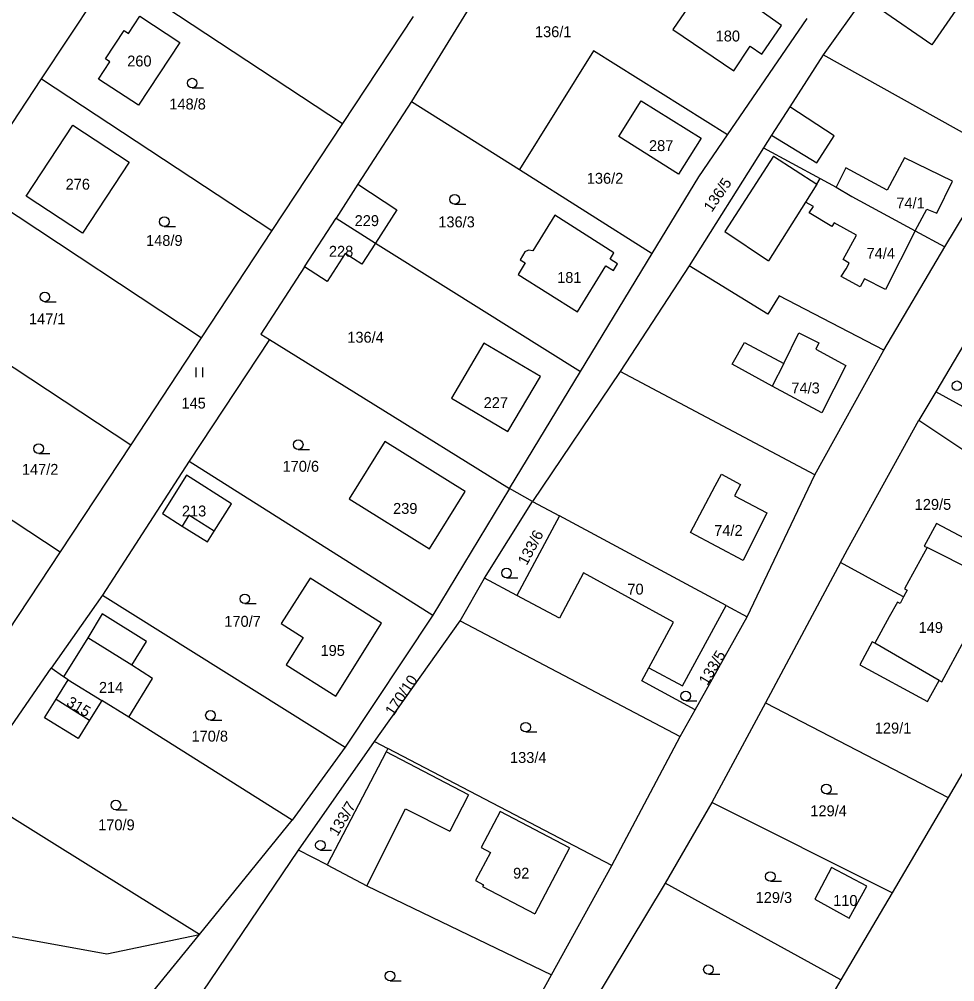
# Model space of a CAD drawing. Extents: x -747333 to -743907, y -1134120 to -1130051.
# Drawn here: x -746482.5 to -746336.6, y -1131946.1 to -1131796 of the extents above; entities that cross this region are included whole.
import ezdxf

# ---------------------------------------------------------------- set-up
doc = ezdxf.new("R2010")
doc.units = 0
for name, color, linetype in [('Hranice parcel', 7, 'Continuous'), ('Parcelní čísla', 7, 'Continuous'), ('Vnitřní kresba', 7, 'Continuous'), ('Značky kultur', 7, 'Continuous')]:
    doc.layers.add(name, color=color, linetype=linetype)

msp = doc.modelspace()

# ---------------------------------------------------------------- linework, layer by layer
at = {"layer": 'Hranice parcel'}
for p, q in [((-746343.18, -1131781.93), (-746357.15, -1131801.57)), ((-746478.99, -1131805.28), (-746467.98, -1131788.59)), ((-746467.98, -1131788.59), (-746432.08, -1131812.26)), ((-746421.07, -1131795.57), (-746432.08, -1131812.26)), ((-746372.05, -1131814.02), (-746359.64, -1131795.9)), ((-746329.51, -1131817), (-746357.15, -1131801.57)), ((-746490, -1131821.98), (-746478.99, -1131805.28)), ((-746478.99, -1131805.28), (-746443.09, -1131828.96)), ((-746421.32, -1131808.85), (-746429.68, -1131821.74)), ((-746421.32, -1131808.85), (-746404.51, -1131819.44)), ((-746432.08, -1131812.26), (-746443.09, -1131828.96)), ((-746366.45, -1131816.06), (-746378.06, -1131834.44)), ((-746338.17, -1131831.49), (-746329.51, -1131817)), ((-746404.51, -1131819.44), (-746383.82, -1131832.55)), ((-746429.68, -1131821.74), (-746433.1, -1131827.02)), ((-746454.1, -1131845.66), (-746490, -1131821.98)), ((-746438.01, -1131834.6), (-746433.1, -1131827.02)), ((-746433.1, -1131827.02), (-746426.94, -1131830.89)), ((-746443.09, -1131828.96), (-746454.1, -1131845.66)), ((-746426.94, -1131830.89), (-746429.05, -1131834.18)), ((-746347.69, -1131847.59), (-746338.17, -1131831.49)), ((-746394.96, -1131850.9), (-746383.82, -1131832.55)), ((-746438.01, -1131834.6), (-746444.83, -1131845.11)), ((-746434.48, -1131836.9), (-746438.01, -1131834.6)), ((-746378.06, -1131834.44), (-746388.82, -1131850.94)), ((-746501.01, -1131838.68), (-746465.11, -1131862.35)), ((-746332.13, -1131841.46), (-746339.57, -1131854.09)), ((-746454.1, -1131845.66), (-746465.11, -1131862.35)), ((-746444.83, -1131845.11), (-746443.47, -1131845.95)), ((-746443.47, -1131845.95), (-746455.99, -1131864.91)), ((-746358.44, -1131867.04), (-746347.69, -1131847.59)), ((-746406.07, -1131869.18), (-746394.96, -1131850.9)), ((-746388.82, -1131850.94), (-746402.47, -1131871.17)), ((-746358.44, -1131867.04), (-746388.82, -1131850.94)), ((-746339.57, -1131854.09), (-746342.22, -1131858.51)), ((-746334.77, -1131856.76), (-746339.57, -1131854.09)), ((-746512.02, -1131855.37), (-746476.13, -1131879.05)), ((-746342.22, -1131858.51), (-746319.24, -1131873.86)), ((-746465.11, -1131862.35), (-746476.13, -1131879.05)), ((-746455.99, -1131864.91), (-746418.01, -1131888.89)), ((-746369.01, -1131889.16), (-746358.44, -1131867.04)), ((-746406.07, -1131869.18), (-746418.01, -1131888.89)), ((-746402.47, -1131871.17), (-746406.07, -1131869.18)), ((-746409.94, -1131883.15), (-746402.47, -1131871.17)), ((-746402.47, -1131871.17), (-746398.27, -1131873.41)), ((-746398.27, -1131873.41), (-746404.9, -1131885.84)), ((-746372.28, -1131887.39), (-746398.27, -1131873.41)), ((-746476.13, -1131879.05), (-746487.14, -1131895.74)), ((-746413.73, -1131889.78), (-746409.94, -1131883.15)), ((-746404.9, -1131885.84), (-746409.94, -1131883.15)), ((-746469.48, -1131885.78), (-746477.5, -1131897.18)), ((-746469.48, -1131885.78), (-746431.68, -1131909.51)), ((-746372.28, -1131887.39), (-746369.01, -1131889.16)), ((-746418.01, -1131888.89), (-746431.68, -1131909.51)), ((-746377.12, -1131903.66), (-746369.01, -1131889.16)), ((-746427.09, -1131908.61), (-746413.73, -1131889.78)), ((-746413.73, -1131889.78), (-746379.44, -1131907.81)), ((-746475.58, -1131898.52), (-746477.5, -1131897.18)), ((-746474.85, -1131898.97), (-746475.58, -1131898.52)), ((-746474.85, -1131898.97), (-746469.61, -1131902.21)), ((-746377.12, -1131903.66), (-746385.43, -1131899.17)), ((-746465.42, -1131904.8), (-746469.61, -1131902.21)), ((-746366.14, -1131902.59), (-746374.51, -1131918.11)), ((-746366.14, -1131902.59), (-746337.68, -1131917.35)), ((-746379.44, -1131907.81), (-746377.12, -1131903.66)), ((-746439.92, -1131920.87), (-746465.42, -1131904.8)), ((-746438.95, -1131925.52), (-746427.09, -1131908.61)), ((-746427.09, -1131908.61), (-746425.01, -1131909.7)), ((-746390.09, -1131927.94), (-746379.44, -1131907.81)), ((-746431.68, -1131909.51), (-746439.92, -1131920.87)), ((-746390.09, -1131927.94), (-746425.01, -1131909.7)), ((-746337.68, -1131917.35), (-746346.4, -1131932.2)), ((-746374.51, -1131918.11), (-746381.8, -1131930.69)), ((-746346.4, -1131932.2), (-746374.51, -1131918.11)), ((-746454.36, -1131938.7), (-746439.92, -1131920.87)), ((-746453.89, -1131947.67), (-746438.95, -1131925.52)), ((-746434.5, -1131927.85), (-746438.95, -1131925.52)), ((-746434.5, -1131927.85), (-746428.29, -1131931.1)), ((-746399.53, -1131945), (-746390.09, -1131927.94)), ((-746428.29, -1131931.1), (-746399.53, -1131945)), ((-746381.8, -1131930.69), (-746395.75, -1131953.81)), ((-746354.37, -1131945.76), (-746381.8, -1131930.69)), ((-746346.4, -1131932.2), (-746354.37, -1131945.76)), ((-746461.71, -1131947.7), (-746454.36, -1131938.7)), ((-746408.25, -1131960.77), (-746399.53, -1131945)), ((-746354.37, -1131945.76), (-746356.8, -1131949.89))]:
    msp.add_line(p, q, dxfattribs=at)
for points in [[(-746397.28, -1131770.07), (-746409.98, -1131790.4), (-746421.32, -1131808.85)], [(-746363.67, -1131796.98), (-746374.76, -1131789.08), (-746380.59, -1131797.61), (-746371.1, -1131804.04), (-746368.51, -1131800.22), (-746366.72, -1131801.44), (-746363.67, -1131796.98)], [(-746466.13, -1131797.76), (-746465.44, -1131798.22), (-746463.66, -1131795.54), (-746457.45, -1131799.62), (-746463.9, -1131809.41), (-746470.12, -1131805.34), (-746468.34, -1131802.64), (-746469.02, -1131802.17), (-746466.13, -1131797.76)], [(-746372.05, -1131814.02), (-746392.96, -1131800.95), (-746404.51, -1131819.44)], [(-746357.15, -1131801.57), (-746362.37, -1131809.67), (-746365.19, -1131814.06), (-746366.45, -1131816.06)], [(-746379.7, -1131820.14), (-746389, -1131814.31), (-746385.5, -1131808.73), (-746376.19, -1131814.56), (-746379.7, -1131820.14)], [(-746481.4, -1131823.61), (-746474.14, -1131812.54), (-746465.37, -1131818.3), (-746472.64, -1131829.35), (-746481.4, -1131823.61)], [(-746383.82, -1131832.55), (-746376.54, -1131820.58), (-746372.05, -1131814.02)], [(-746366.45, -1131816.06), (-746357.6, -1131820.84), (-746355.14, -1131822.17), (-746352.66, -1131823.64), (-746342.8, -1131829.01), (-746338.17, -1131831.49)], [(-746429.68, -1131821.74), (-746423.64, -1131825.73), (-746426.94, -1131830.89)], [(-746389.76, -1131832.4), (-746399, -1131826.54), (-746402.44, -1131832.12)], [(-746426.94, -1131830.89), (-746415.96, -1131837.77), (-746394.96, -1131850.9)], [(-746402.44, -1131832.12), (-746403.09, -1131832), (-746403.68, -1131832.25), (-746404.4, -1131833.49), (-746403.6, -1131833.99)], [(-746429.05, -1131834.18), (-746431.65, -1131832.5), (-746434.48, -1131836.9)], [(-746395.45, -1131841.62), (-746391.02, -1131834.44), (-746389.86, -1131835.15), (-746389.23, -1131834.12), (-746390.38, -1131833.41), (-746389.76, -1131832.4)], [(-746403.6, -1131833.99), (-746404.71, -1131835.79), (-746395.45, -1131841.62)], [(-746347.69, -1131847.59), (-746363.99, -1131839.14), (-746365.8, -1131841.96), (-746378.06, -1131834.44)], [(-746443.47, -1131845.95), (-746427.32, -1131855.97), (-746406.07, -1131869.18)], [(-746406.32, -1131860.29), (-746401.23, -1131851.72), (-746410.03, -1131846.49), (-746415.09, -1131855.08), (-746406.32, -1131860.29)], [(-746354.46, -1131880.72), (-746353.37, -1131878.68), (-746342.22, -1131858.51)], [(-746412.97, -1131869.62), (-746425.5, -1131861.83), (-746431.03, -1131870.79), (-746418.52, -1131878.56), (-746412.97, -1131869.62)], [(-746455.99, -1131864.91), (-746466.63, -1131881.37), (-746469.48, -1131885.78)], [(-746452.09, -1131875.82), (-746449.39, -1131871.54), (-746456.41, -1131867.08), (-746460.17, -1131873.04), (-746457.09, -1131875.01), (-746453.14, -1131877.48), (-746452.09, -1131875.82)], [(-746333.74, -1131890.21), (-746330.25, -1131883.74), (-746330.66, -1131883.52), (-746328.89, -1131880.25), (-746339.47, -1131874.63), (-746341.38, -1131878.14), (-746340.94, -1131878.38), (-746343.79, -1131883.58), (-746344.46, -1131884.81), (-746344.04, -1131885.02), (-746344.6, -1131886.06)], [(-746354.46, -1131880.72), (-746364.94, -1131900.36), (-746366.14, -1131902.59)], [(-746344.6, -1131886.06), (-746346.67, -1131884.94), (-746354.46, -1131880.72)], [(-746433.13, -1131901.53), (-746426.01, -1131890.18), (-746437.12, -1131883.14), (-746441.65, -1131890.22)], [(-746344.6, -1131886.06), (-746345.17, -1131887.1), (-746345.57, -1131886.87), (-746346.84, -1131889.17), (-746349.1, -1131893.27), (-746349.5, -1131893.05), (-746351.45, -1131896.64), (-746340.87, -1131902.35), (-746339.07, -1131899.09), (-746338.66, -1131899.32), (-746335.16, -1131892.84)], [(-746385.43, -1131899.17), (-746384.32, -1131897.11), (-746379.07, -1131899.95), (-746372.28, -1131887.39)], [(-746465.42, -1131904.8), (-746461.69, -1131898.76), (-746464.95, -1131896.72), (-746462.62, -1131892.99), (-746469.56, -1131888.71), (-746471.81, -1131892.44), (-746475.58, -1131898.52)], [(-746441.65, -1131890.22), (-746438.2, -1131892.39), (-746440.88, -1131896.67), (-746433.13, -1131901.53)], [(-746454.36, -1131938.7), (-746469.66, -1131929.19), (-746490.63, -1131916.16), (-746477.5, -1131897.18)], [(-746469.61, -1131902.21), (-746471.53, -1131905.27), (-746473.31, -1131908.12), (-746478.56, -1131904.89), (-746476.75, -1131902), (-746474.85, -1131898.97)], [(-746545.06, -1131905.46), (-746551.21, -1131914.79), (-746552.36, -1131918.38), (-746542.1, -1131920.25), (-746542.46, -1131922.22), (-746512.94, -1131927.58), (-746514.01, -1131933.49), (-746468.81, -1131941.71), (-746454.36, -1131938.7)], [(-746331.51, -1131906.85), (-746336.79, -1131915.84), (-746337.68, -1131917.35)], [(-746425.01, -1131909.7), (-746425.29, -1131910.22), (-746434.5, -1131927.85)], [(-746350.32, -1131931.16), (-746355.85, -1131928.24), (-746358.46, -1131933.16), (-746353.09, -1131936.15), (-746350.32, -1131931.16)]]:
    msp.add_lwpolyline(points, dxfattribs=at)
at = {"layer": 'Vnitřní kresba'}
for p, q in [((-746355.46, -1131814.18), (-746362.37, -1131809.67)), ((-746365.19, -1131814.06), (-746358.15, -1131818.41)), ((-746358.15, -1131818.41), (-746355.46, -1131814.18)), ((-746364.87, -1131817.35), (-746372.49, -1131829.12)), ((-746364.87, -1131817.35), (-746358.14, -1131821.7)), ((-746344.47, -1131817.61), (-746347.15, -1131822.64)), ((-746336.96, -1131821.23), (-746344.47, -1131817.61)), ((-746353.59, -1131819.15), (-746355.14, -1131822.17)), ((-746347.15, -1131822.64), (-746353.59, -1131819.15)), ((-746358.14, -1131821.7), (-746359.91, -1131824.5)), ((-746358.14, -1131821.7), (-746357.6, -1131820.84)), ((-746339.44, -1131826.26), (-746336.96, -1131821.23)), ((-746359.91, -1131824.5), (-746365.69, -1131833.66)), ((-746358.68, -1131825.18), (-746359.91, -1131824.5)), ((-746359.31, -1131826.21), (-746358.68, -1131825.18)), ((-746355.81, -1131828.32), (-746359.31, -1131826.21)), ((-746342.8, -1131829.01), (-746340.98, -1131825.59)), ((-746340.98, -1131825.59), (-746339.44, -1131826.26)), ((-746355.43, -1131827.75), (-746355.81, -1131828.32)), ((-746351.94, -1131829.66), (-746355.43, -1131827.75)), ((-746372.49, -1131829.12), (-746365.69, -1131833.66)), ((-746342.8, -1131829.01), (-746347.43, -1131838.14)), ((-746354.01, -1131833.47), (-746351.94, -1131829.66)), ((-746353.11, -1131834.02), (-746354.01, -1131833.47)), ((-746354.32, -1131836.11), (-746353.54, -1131834.9)), ((-746353.54, -1131834.9), (-746353.11, -1131834.02)), ((-746351.37, -1131837.7), (-746354.32, -1131836.11)), ((-746350.68, -1131836.47), (-746351.37, -1131837.7)), ((-746347.43, -1131838.14), (-746350.68, -1131836.47)), ((-746363.27, -1131849.66), (-746360.93, -1131844.9)), ((-746360.93, -1131844.9), (-746357.84, -1131846.44)), ((-746371.32, -1131849.8), (-746369.44, -1131846.38)), ((-746369.44, -1131846.38), (-746363.27, -1131849.66)), ((-746357.84, -1131846.44), (-746358.31, -1131847.45)), ((-746358.31, -1131847.45), (-746353.62, -1131850)), ((-746365.09, -1131853.19), (-746371.32, -1131849.8)), ((-746363.27, -1131849.66), (-746365.09, -1131853.19)), ((-746353.62, -1131850), (-746357.37, -1131857.38)), ((-746357.37, -1131857.38), (-746365.09, -1131853.19)), ((-746374.01, -1131868.72), (-746373, -1131866.91)), ((-746373, -1131866.91), (-746370.05, -1131868.52)), ((-746377.83, -1131876.03), (-746374.01, -1131868.72)), ((-746370.05, -1131868.52), (-746370.98, -1131870.31)), ((-746370.98, -1131870.31), (-746365.95, -1131872.95)), ((-746456.02, -1131873.33), (-746457.09, -1131875.01)), ((-746452.09, -1131875.82), (-746456.02, -1131873.33)), ((-746365.95, -1131872.95), (-746369.63, -1131880.4)), ((-746369.63, -1131880.4), (-746377.83, -1131876.03)), ((-746330.66, -1131883.52), (-746340.94, -1131878.38)), ((-746394.49, -1131882.3), (-746398.26, -1131889.38)), ((-746380.47, -1131889.98), (-746394.49, -1131882.3)), ((-746398.26, -1131889.38), (-746404.9, -1131885.84)), ((-746384.32, -1131897.11), (-746380.47, -1131889.98)), ((-746464.95, -1131896.72), (-746471.81, -1131892.44)), ((-746339.07, -1131899.09), (-746349.1, -1131893.27)), ((-746476.75, -1131902), (-746471.53, -1131905.27)), ((-746412.42, -1131916.94), (-746425.29, -1131910.22)), ((-746412.42, -1131916.94), (-746415.37, -1131922.58)), ((-746428.29, -1131931.1), (-746422.28, -1131919.11)), ((-746422.28, -1131919.11), (-746415.37, -1131922.58)), ((-746407.53, -1131919.5), (-746410.48, -1131925.14)), ((-746396.69, -1131925.16), (-746407.53, -1131919.5)), ((-746410.48, -1131925.14), (-746409.03, -1131925.9)), ((-746396.69, -1131925.16), (-746402.08, -1131935.48)), ((-746409.03, -1131925.9), (-746411.35, -1131930.29)), ((-746411.35, -1131930.29), (-746410.1, -1131930.95)), ((-746410.1, -1131930.95), (-746410.24, -1131931.22)), ((-746410.24, -1131931.22), (-746402.08, -1131935.48))]:
    msp.add_line(p, q, dxfattribs=at)
msp.add_lwpolyline([(-746333.21, -1131789.79), (-746340.23, -1131799.97), (-746348.05, -1131794.58), (-746341.05, -1131784.42), (-746333.21, -1131789.79)], dxfattribs=at)
at = {"layer": 'Značky kultur'}
for p, q in [((-746455.523, -1131806.71), (-746453.773, -1131806.71)), ((-746414.603, -1131824.84), (-746412.853, -1131824.84)), ((-746459.873, -1131828.32), (-746458.123, -1131828.32)), ((-746478.493, -1131840.04), (-746476.743, -1131840.04)), ((-746454.881, -1131851.82), (-746454.881, -1131850.32)), ((-746453.88, -1131851.82), (-746453.88, -1131850.32)), ((-746479.453, -1131863.7), (-746477.703, -1131863.7)), ((-746438.993, -1131863.07), (-746437.243, -1131863.07)), ((-746406.523, -1131883.08), (-746404.773, -1131883.08)), ((-746447.313, -1131887.11), (-746445.563, -1131887.11)), ((-746378.573, -1131902.27), (-746376.823, -1131902.27)), ((-746452.673, -1131905.27), (-746450.923, -1131905.27)), ((-746403.523, -1131907.12), (-746401.773, -1131907.12)), ((-746356.653, -1131916.77), (-746354.903, -1131916.77)), ((-746467.423, -1131919.24), (-746465.673, -1131919.24)), ((-746435.533, -1131925.52), (-746433.783, -1131925.52)), ((-746365.383, -1131930.4), (-746363.633, -1131930.4)), ((-746424.673, -1131945.9), (-746422.923, -1131945.9)), ((-746375.033, -1131944.9), (-746373.283, -1131944.9))]:
    msp.add_line(p, q, dxfattribs=at)
for centre in [(-746455.523, -1131805.96), (-746414.603, -1131824.09), (-746459.873, -1131827.57), (-746478.493, -1131839.29), (-746336.303, -1131853.15), (-746479.453, -1131862.95), (-746438.993, -1131862.32), (-746406.523, -1131882.33), (-746447.313, -1131886.36), (-746378.573, -1131901.52), (-746452.673, -1131904.52), (-746403.523, -1131906.37), (-746356.653, -1131916.02), (-746467.423, -1131918.49), (-746435.533, -1131924.77), (-746365.383, -1131929.65), (-746424.673, -1131945.15), (-746375.033, -1131944.15)]:
    msp.add_circle(centre, 0.75, dxfattribs=at)

# ---------------------------------------------------------------- texts
at = {"layer": 'Parcelní čísla'}
for s, p in [('136/1', (-746402.08, -1131798.8)), ('180', (-746373.91, -1131799.47)), ('260', (-746465.654, -1131803.37)), ('148/8', (-746459.083, -1131810.07)), ('287', (-746384.304, -1131816.56)), ('136/2', (-746394, -1131821.65)), ('276', (-746475.254, -1131822.57)), ('74/1', (-746345.74, -1131825.5)), ('229', (-746430.194, -1131828.25)), ('136/3', (-746417.15, -1131828.45)), ('148/9', (-746462.713, -1131831.34)), ('228', (-746434.204, -1131833.03)), ('74/4', (-746350.38, -1131833.35)), ('181', (-746398.62, -1131837.11)), ('147/1', (-746480.973, -1131843.57)), ('136/4', (-746431.34, -1131846.43)), ('74/3', (-746362.1, -1131854.34)), ('145', (-746457.194, -1131856.7)), ('227', (-746410.08, -1131856.63)), ('147/2', (-746482.073, -1131867.03)), ('170/6', (-746441.43, -1131866.55)), ('129/5', (-746342.88, -1131872.49)), ('213', (-746457.13, -1131873.52)), ('239', (-746424.2, -1131873.12)), ('74/2', (-746374.14, -1131876.55)), ('70', (-746387.67, -1131885.7)), ('170/7', (-746450.51, -1131890.72)), ('149', (-746342.27, -1131891.69)), ('195', (-746435.51, -1131895.26)), ('214', (-746470.06, -1131901.02)), ('129/1', (-746349.1, -1131907.36)), ('170/8', (-746455.63, -1131908.62)), ('133/4', (-746405.97, -1131911.95)), ('129/4', (-746359.15, -1131920.26)), ('170/9', (-746470.18, -1131922.45)), ('92', (-746405.49, -1131929.99)), ('129/3', (-746367.68, -1131933.78)), ('110', (-746355.59, -1131934.24))]:
    msp.add_text(s, height=1.7, dxfattribs=at).set_placement(p)
for s, rotation, p in [('136/5', 56, (-746374.505, -1131826.195)), ('133/6', 62, (-746403.359, -1131881.259)), ('133/5', 59, (-746375.201, -1131899.957)), ('170/10', 56, (-746424.165, -1131904.745)), ('315', 329, (-746475.27, -1131902.921)), ('133/7', 59, (-746432.871, -1131923.487))]:
    msp.add_text(s, height=1.7, rotation=rotation, dxfattribs=at).set_placement(p)

doc.saveas('drawing.dxf')
